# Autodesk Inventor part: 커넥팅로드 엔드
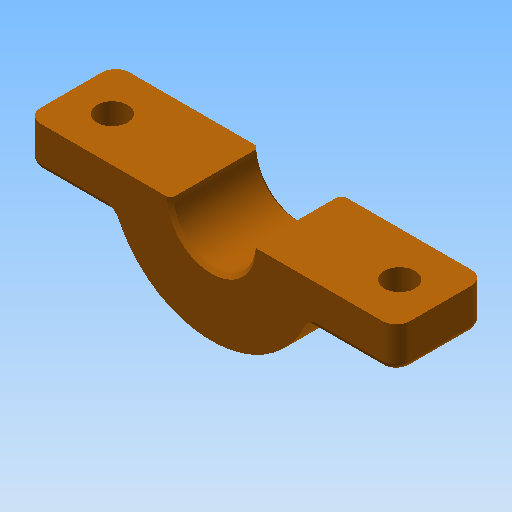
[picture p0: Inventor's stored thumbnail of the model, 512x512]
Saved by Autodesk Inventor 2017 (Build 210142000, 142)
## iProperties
Created: 2016-11
Part Number: 커넥팅로드 엔드
Material: 알루미늄 6061
Document SubType Name: Modeling
Designer: mduedu
Density: 2.71 g/cm^3
Mass: 15.0819 g
Surface Area: 26.6719 cm^2
Volume: 5.56529 cm^3
Appearance: 주황색
Author: mduedu
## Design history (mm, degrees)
sketch "스케치1" dims "d0" = 30, "d3" = 15
  geometry: L1 (0, 0)-(0, 96); L2 (-5, 90.41)-(-10, 11.18); L3 (5, 90.41)-(10, 11.18); C1 r 6 at (0, 0); C2 r 4 at (0, 96); 3 further points
  constraints: 6 end point, 4 coincident, 2 centre point, 2 symmetric about line, 1 vertical, 6 other
  dimensions: "d1" = 12 diameter of C1; "d2" = 8 diameter of C2; "d4" = 96 distance of L1.start L1.end; "d6" = 10 distance from line of L1 L2.end; "d7" = 5 distance from line of L1 L2.start
extrude "돌출1" new body sketch "스케치1" stored distance "d8" = 13; taper "d9" = 0 deg
extrude "돌출2" join sketch "스케치1" stored distance "d10" = 32; taper "d11" = 0 deg
sketch "스케치2"
  geometry: L1 (5, 90.41)-(10, 11.18) reference; L2 (-5, 90.41)-(-10, 11.18) reference; A1 r 7.5 centre (0, 96) between (5, 90.41) and (-5, 90.41) reference; A2 r 15 centre (0, 0) between (10, 11.18) and (-10, 11.18) reference
extrude "돌출3" join sketch "스케치2" stored distance "d12" = 8; taper "d13" = 0 deg
sketch "스케치3"
  geometry: L1 (-2.732, 78.715)-(-6.171, 24.226); L2 (2.732, 78.715)-(6.171, 24.226); L3 (0, 78.5)-(0, 25); A1 r 17.5 centre (0, 96) between (-2.732, 78.715) and (2.732, 78.715); A2 r 25 centre (0, 0) between (6.171, 24.226) and (-6.171, 24.226); 9 further points; 2 other entities
  constraints: 6 end point, 6 point on circle, 2 centre point, 1 symmetric about line, 1 vertical alignment, 6 other
  dimensions: "d18" = 10 dimension on A1; "d19" = 10 dimension on A2; "d20" = 3 dimension on L1
extrude "돌출4" cut sketch "스케치3" distance "d21" = 2; taper "d22" = 0 deg
fillet "모깎기1" dims "d23" = 2
fillet "모깎기2" dims "d24" = 2
fillet "모깎기3" dims "d25" = 1
chamfer "모따기1" distance "d26" = 0.5; stored, may be unused: second distance "d27" = 2, angle "d28" = 45 deg
sketch "스케치4"
  geometry: L1 (-27, -6)-(-13.748, -6); L2 (27, -6)-(27, 6); L3 (27, 6)-(13.748, 6); L4 (-27, 6)-(-27, -6); L5 (-27, -6)-(27, 6); L6 (27, -6)-(-27, 6); L7 (-13.748, 6)-(-27, 6); L8 (13.748, 6)-(-13.748, 6); L9 (13.748, -6)-(27, -6); L10 (-13.748, -6)-(13.748, -6); A1 r 15 centre (0, 0) between (-13.748, 6) and (13.748, 6) reference; 1 further point
  constraints: 20 end point, 10 parallel, 4 point on circle, 3 horizontal, 3 perpendicular, 2 midpoint
  dimensions: "d29" = 54 distance of L1.start L2.start; "d31" = 12 distance of L2.start L2.end
extrude "돌출5" join sketch "스케치4" stored distance "d32" = 0; taper "d33" = 0 deg
fillet "모깎기4" dims "d34" = 2
fillet "모깎기5" dims "d35" = 1
fillet "모깎기6" dims "d36" = 1
sketch "스케치5"
  geometry: L1 (1, 0)-(1, 9) reference; L2 (-18.5, 20.5)-(-33.5, 20.5) reference; L3 (-33.5, -11.5)-(-18.5, -11.5) reference; L4 (-26, 20.5)-(-26, -11.5); 3 further points
  constraints: 2 end point, 2 midpoint, 1 horizontal alignment, 1 symmetric about line
  dimensions: "d37" = 6 distance from line of point (-5, 4.5) L1
feature "분할1"
sketch "스케치7"
  geometry: 2 further points
  constraints: 2 other
hole "구멍2" sketch "스케치7" at (-47, 4.5), (-5, 4.5) diameter "d45" = 4.5; stored, may be unused: countersink angle "d49" = 90 deg, drill point angle "d51" = 0 deg; dims "d46" = 6, "d47" = 4, "d48" = 2, "d50" = 8
node "솔리드1"
mirror "대칭1"
other parameters: "d16" = 4, "d17" = 4
